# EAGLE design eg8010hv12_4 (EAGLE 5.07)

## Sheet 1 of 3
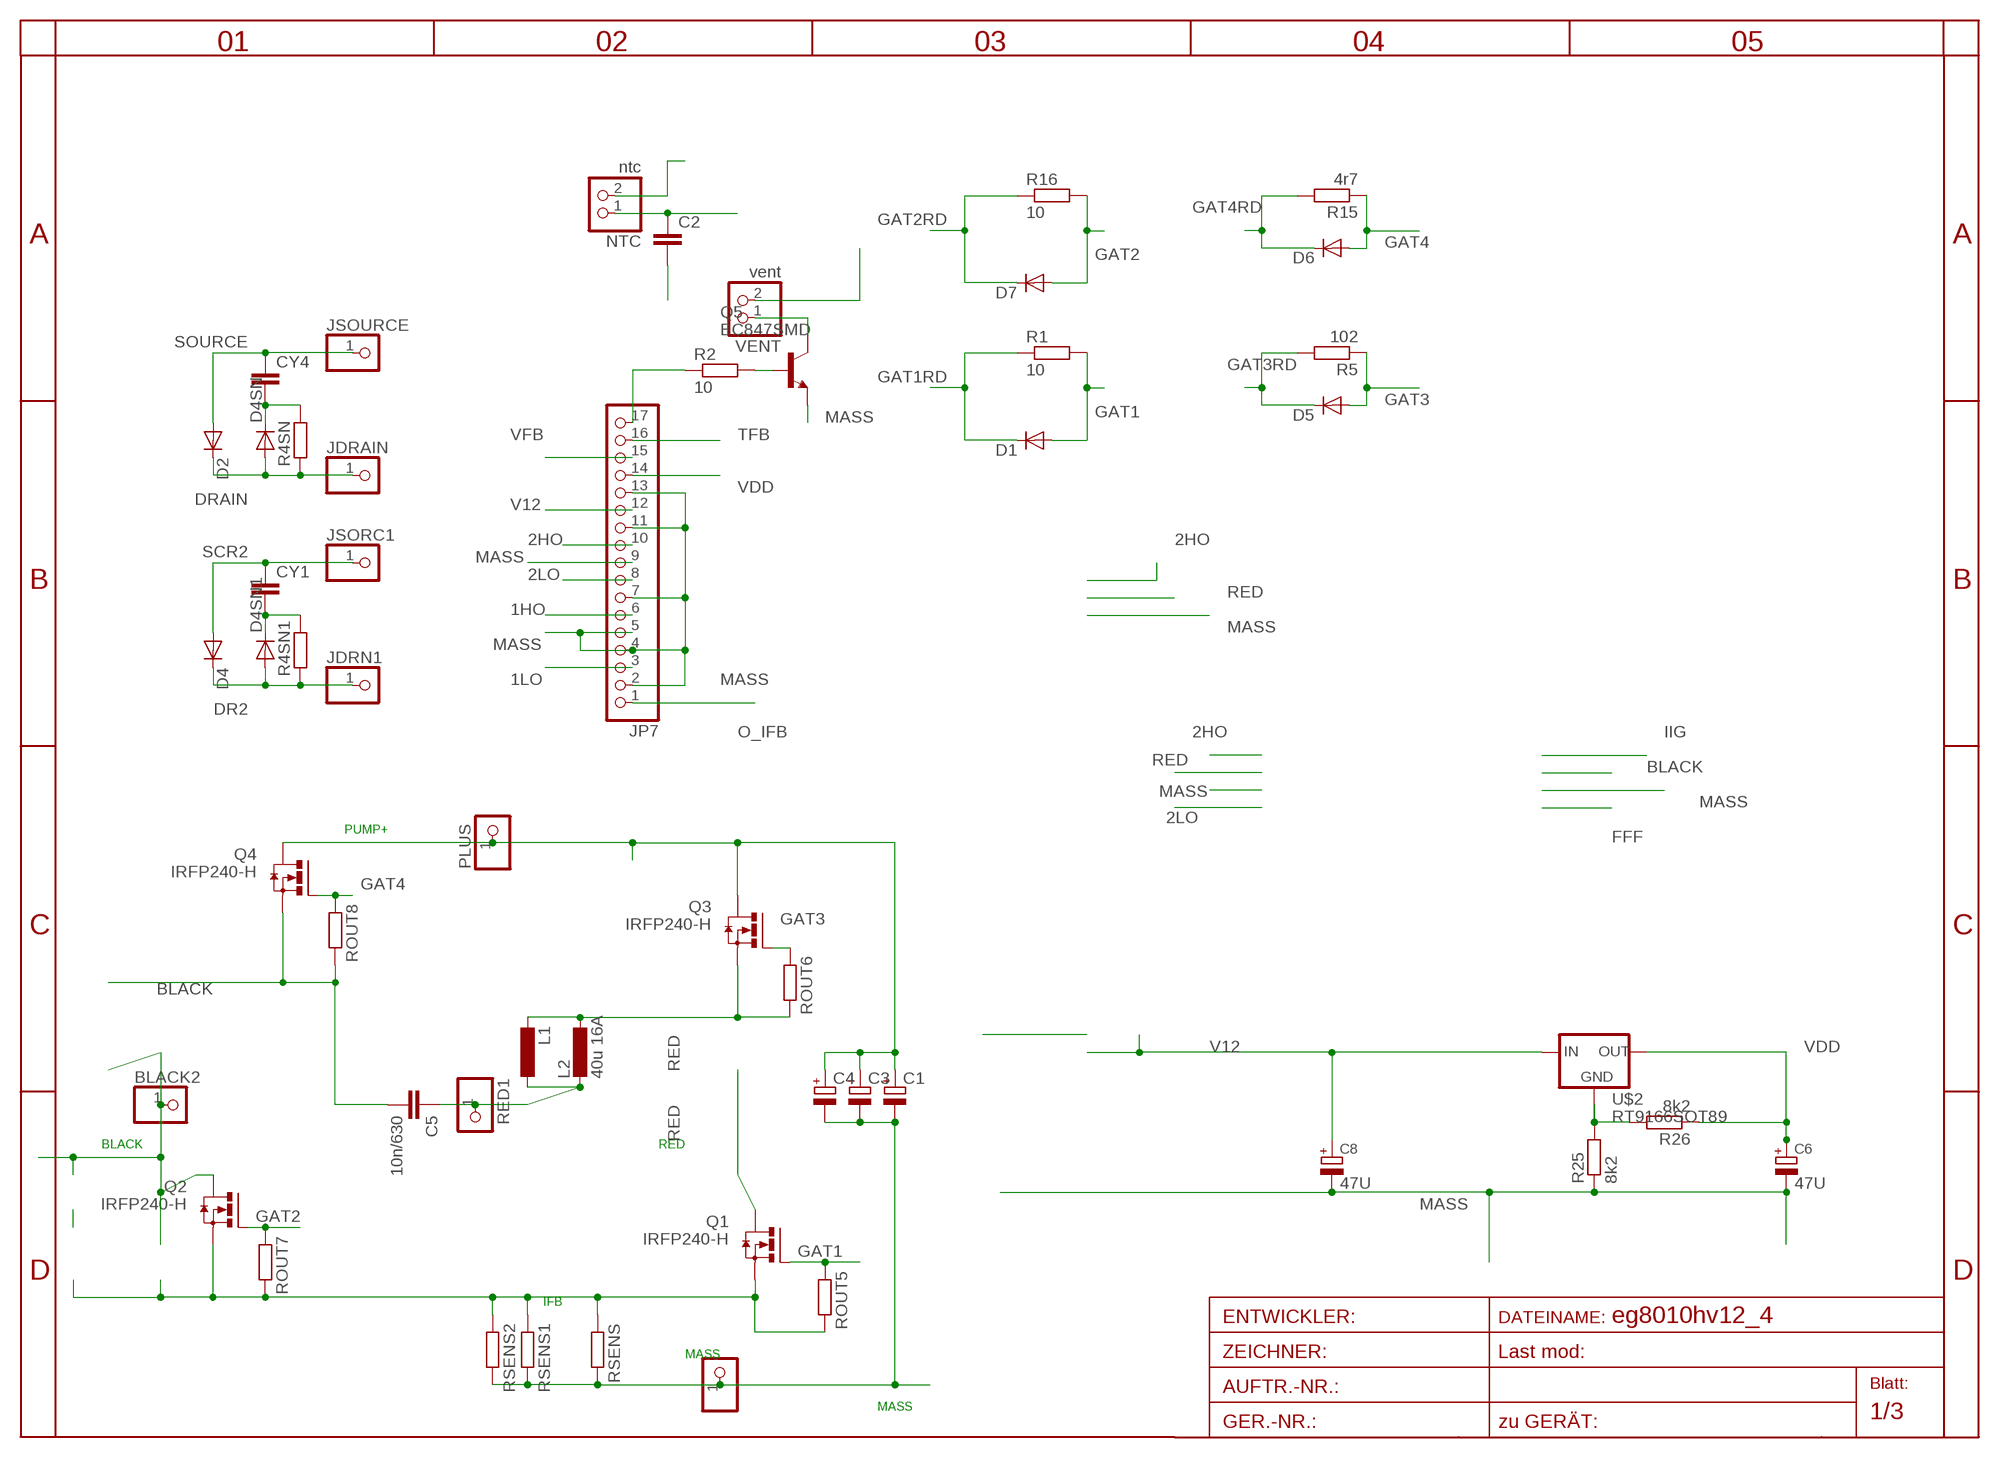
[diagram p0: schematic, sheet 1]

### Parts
BLACK2  PINHD-1X12MM3  [1X2MM3]
C1  CPOL-EUE5-13  [E5-13]
C2  C-EUC1206  [C1206]
C3  CPOL-EUE5-13  [E5-13]
C4  CPOL-EUE5-13  [E5-13]
C5  10n/630  C-EU275-173X316  [C275-173X316]
C6  47U  CPOL-EUSMCA  [SMC_A]
C8  47U  CPOL-EUSMCA  [SMC_A]
CY1  CXXC10B5  [XC10B5]
CY4  CXXC10B5  [XC10B5]
D1  DIODE-SMA-DO214  [SMA-DO214AC]
D2  DIODE-SMC  [SMC]
D4  DIODE-SMC  [SMC]
D4SN  DIODE-P1-10  [P1-10]
D4SN1  DIODE-P1-10  [P1-10]
D5  DIODE-MINIMELF  [MINIMELF]
D6  DIODE-SMA-DO214  [SMA-DO214AC]
D7  DIODE-SMA-DO214  [SMA-DO214AC]
JDRAIN  PINHD-1X11MM0  [1X1MM0]
JDRN1  PINHD-1X11MM0  [1X1MM0]
JP7  PINHD-1X17  [1X17]
JSORC1  PINHD-1X11MM0  [1X1MM0]
JSOURCE  PINHD-1X11MM0  [1X1MM0]
L1  L-EU4.13  [0204/13]
L2  40u 16A  L-EURNG  [RING]
MINUS  PINHD-1X12MM3  [1X2MM3]
NTC  ntc  PINHD-1X2STR  [1X02]
PLUS  PINHD-1X12MM3  [1X2MM3]
Q1  IRFP240-H  [TO247BH]
Q2  IRFP240-H  [TO247BH]
Q3  IRFP240-H  [TO247BH]
Q4  IRFP240-H  [TO247BH]
Q5  BC847SMD  [SOT23]
R1  10  R-EU_R1206  [R1206]
R2  10  R-EU_R0805  [R0805]
R4SN  R-EU_0207/10  [0207/10]
R4SN1  R-EU_0207/10  [0207/10]
R5  102  R-EU_R1206  [R1206]
R15  4r7  R-EU_R1206  [R1206]
R16  10  R-EU_R1206  [R1206]
R25  8k2  R-EU_R0805  [R0805]
R26  8k2  R-EU_R0805  [R0805]
RED1  PINHD-1X12MM3  [1X2MM3]
ROUT5  R-EU_R1206  [R1206]
ROUT6  R-EU_R1206  [R1206]
ROUT7  R-EU_R1206  [R1206]
ROUT8  R-EU_R1206  [R1206]
RSENS  R-EU_0204/7  [0204/7]
RSENS1  R-EU_0204/7  [0204/7]
RSENS2  R-EU_0922V  [0922V]
U$2  RT9166SOT89  [SOT89R]
VENT  vent  PINHD-1X2STR  [1X02]

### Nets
1HO: JP7.6 ; also sheet 3
1LO: JP7.3 ; also sheet 3
2HO: JP7.10 ; also sheet 3
2LO: JP7.8 ; also sheet 3
ACL: C5.1 L1.1 L2.2 RED1.1 ; also sheet 3
BLACK: BLACK2.1 C5.2 Q2.D Q4.S ROUT8.2 ; also sheet 3
DR2: D4.C D4SN1.A JDRN1.1 R4SN1.1
DRAIN: D2.C D4SN.A JDRAIN.1 R4SN.1
FANCTR: JP7.17 R2.1 ; also sheet 3
GAT1: D1.A Q1.G R1.2 ROUT5.1
GAT1RD: D1.K(C) R1.1 ; also sheet 3
GAT2: D7.A Q2.G R16.2 ROUT7.1
GAT2RD: D7.K(C) R16.1 ; also sheet 3
GAT3: D5.A Q3.G R5.1 ROUT6.1
GAT3RD: D5.C R5.2 ; also sheet 3
GAT4: D6.A Q4.G R15.1 ROUT8.1
GAT4RD: D6.K(C) R15.2 ; also sheet 3
IFB: Q1.S Q2.S ROUT5.2 ROUT7.2 RSENS1.1 RSENS2.1 RSENS.1 ; also sheet 2,3
MASS: C1.- C2.2 C3.- C4.- C6.- C8.- JP7.2 JP7.4 JP7.5 JP7.7 JP7.9 JP7.11 JP7.13 MINUS.1 Q5.2(E) R25.1 RSENS1.2 RSENS2.2 RSENS.2 ; also sheet 2,3
N$1: Q5.3(C) VENT.1
N$2: Q5.1(B) R2.2
N$17: R25.2 R26.2 U$2.3(GND) U$2.4(GND1)
O_IFB: JP7.1 ; also sheet 2,3
PUMP+: C1.+ C3.+ C4.+ PLUS.1 Q3.D Q4.D ; also sheet 2
RED: L1.2 L2.1 Q1.D Q3.S ROUT6.2 ; also sheet 3
SCR2: CY1.1 D4.A JSORC1.1
SNUB1: CY1.2 D4SN1.C R4SN1.2
SNUB2: CY4.2 D4SN.C R4SN.2
SOURCE: CY4.1 D2.A JSOURCE.1
TFB: C2.1 JP7.16 NTC.1 ; also sheet 3
V12: C8.+ JP7.12 U$2.1(IN) ; also sheet 2,3
VDD: C6.+ JP7.14 NTC.2 R26.1 U$2.2(OUT) VENT.2 ; also sheet 3
VFB: JP7.15 ; also sheet 3

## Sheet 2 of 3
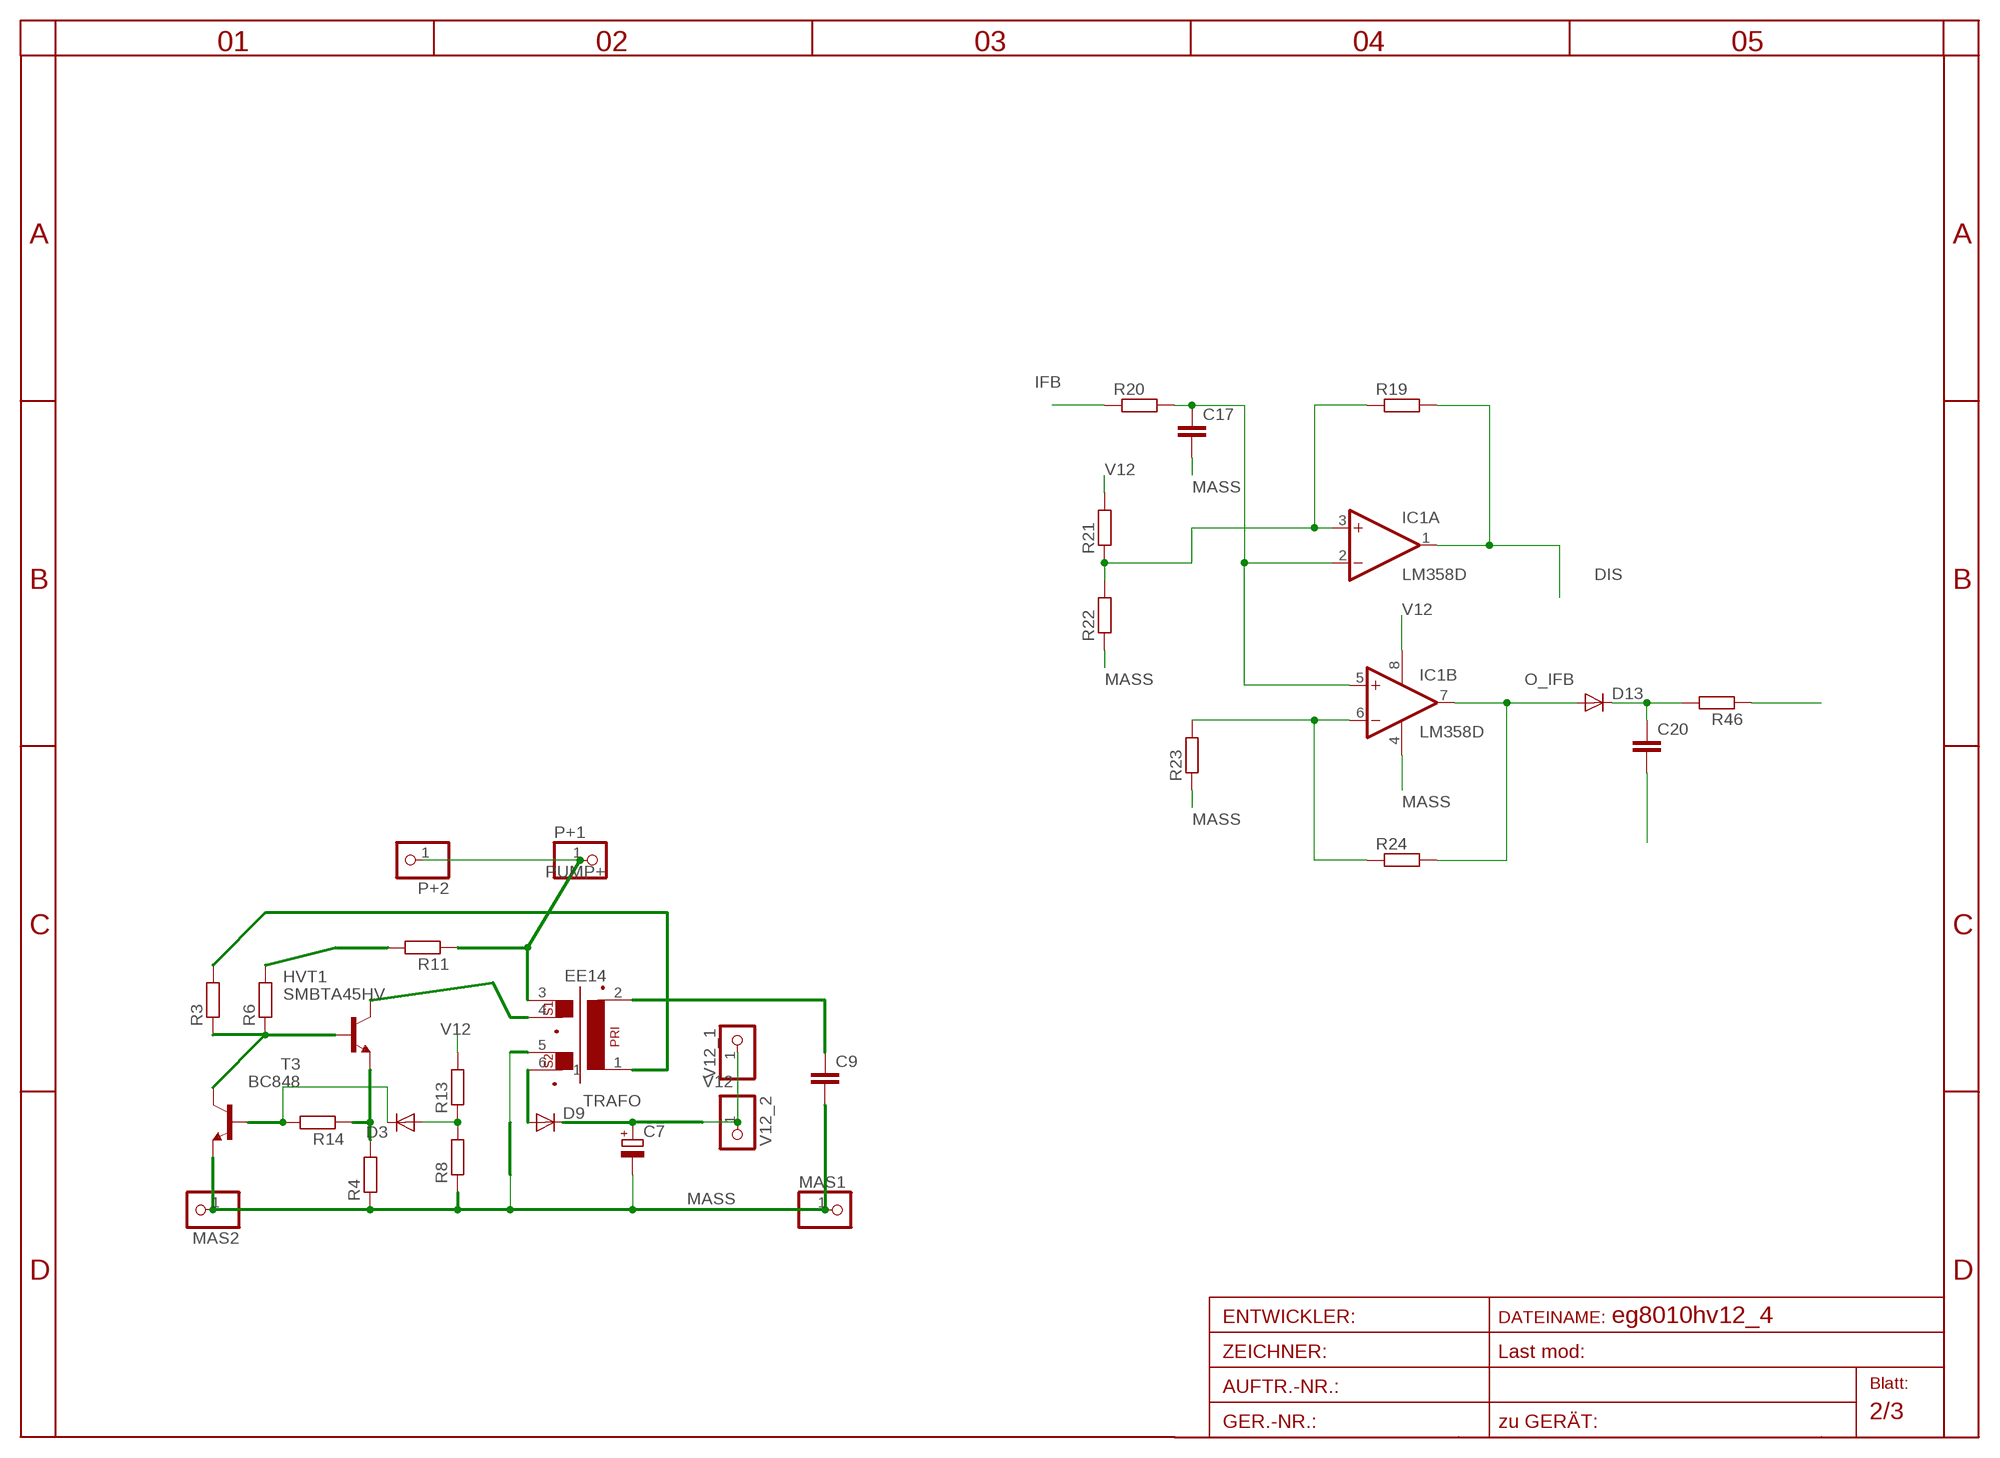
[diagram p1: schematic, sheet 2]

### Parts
C7  CPOL-EUSMCA  [SMC_A]
C9  C-EUC0805  [C0805]
C17  C-EUC1206  [C1206]
C20  C-EUC0805  [C0805]
D3  DIODE-MINIMELF  [MINIMELF]
D9  DIODE-SMA-DO214  [SMA-DO214AC]
D13  DIODE-MINIMELF  [MINIMELF]
HVT1  SMBTA45HV  [SOT23HV]
IC1  LM358D  [SO08]
MAS1  PINHD-1X11X0.4  [1X01]
MAS2  PINHD-1X11X0.4  [1X01]
P+1  PINHD-1X11X0.4  [1X01]
P+2  PINHD-1X11X0.4  [1X01]
R3  R-EU_R0805  [R0805]
R4  R-EU_R0805  [R0805]
R6  R-EU_R1206  [R1206]
R8  R-EU_R0805  [R0805]
R11  R-EU_R1206  [R1206]
R13  R-EU_R0805  [R0805]
R14  R-EU_R0805  [R0805]
R19  R-EU_R1206  [R1206]
R20  R-EU_R0805  [R0805]
R21  R-EU_R0805  [R0805]
R22  R-EU_R0805  [R0805]
R23  R-EU_R0805  [R0805]
R24  R-EU_R0805  [R0805]
R46  R-EU_R0805  [R0805]
T3  BC848  [SOT23]
TRAFO  EE14  [EE14]
V12_1  PINHD-1X11X0.4  [1X01]
V12_2  PINHD-1X11X0.4  [1X01]

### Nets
A: D9.A TRAFO.6
B1C2: HVT1.1(B) R3.1 R6.1 T3.C
BT1: D3.C R14.2 T3.B
C1: HVT1.3(C) TRAFO.4
DIS: IC1.1(A:OUT) R19.2 ; also sheet 3
EB: HVT1.2(E) R4.2 R14.1
IFB: R20.1 ; also sheet 1,3
IFB8010: R46.1 ; also sheet 3
MASS: C7.- C9.2 C17.2 C20.2 IC1.4(P:V-) MAS1.1 MAS2.1 R4.1 R8.1 R22.1 R23.1 T3.E TRAFO.5 ; also sheet 1,3
N$6: R3.2 TRAFO.1
N$7: C9.1 TRAFO.2
N$8: R6.2 R11.2
N$9: IC1.3(A:+IN) R19.1 R21.1 R22.2
N$10: D3.A R8.2 R13.1
N$15: C17.1 IC1.2(A:-IN) IC1.5(B:+IN) R20.2
N$18: IC1.6(B:-IN) R23.2 R24.1
N$40: C20.1 D13.C R46.2
O_IFB: D13.A IC1.7(B:OUT) R24.2 ; also sheet 1,3
PUMP+: P+1.1 P+2.1 R11.1 TRAFO.3 ; also sheet 1
V12: C7.+ D9.K(C) IC1.8(P:V+) R13.2 R21.2 V12_1.1 V12_2.1 ; also sheet 1,3

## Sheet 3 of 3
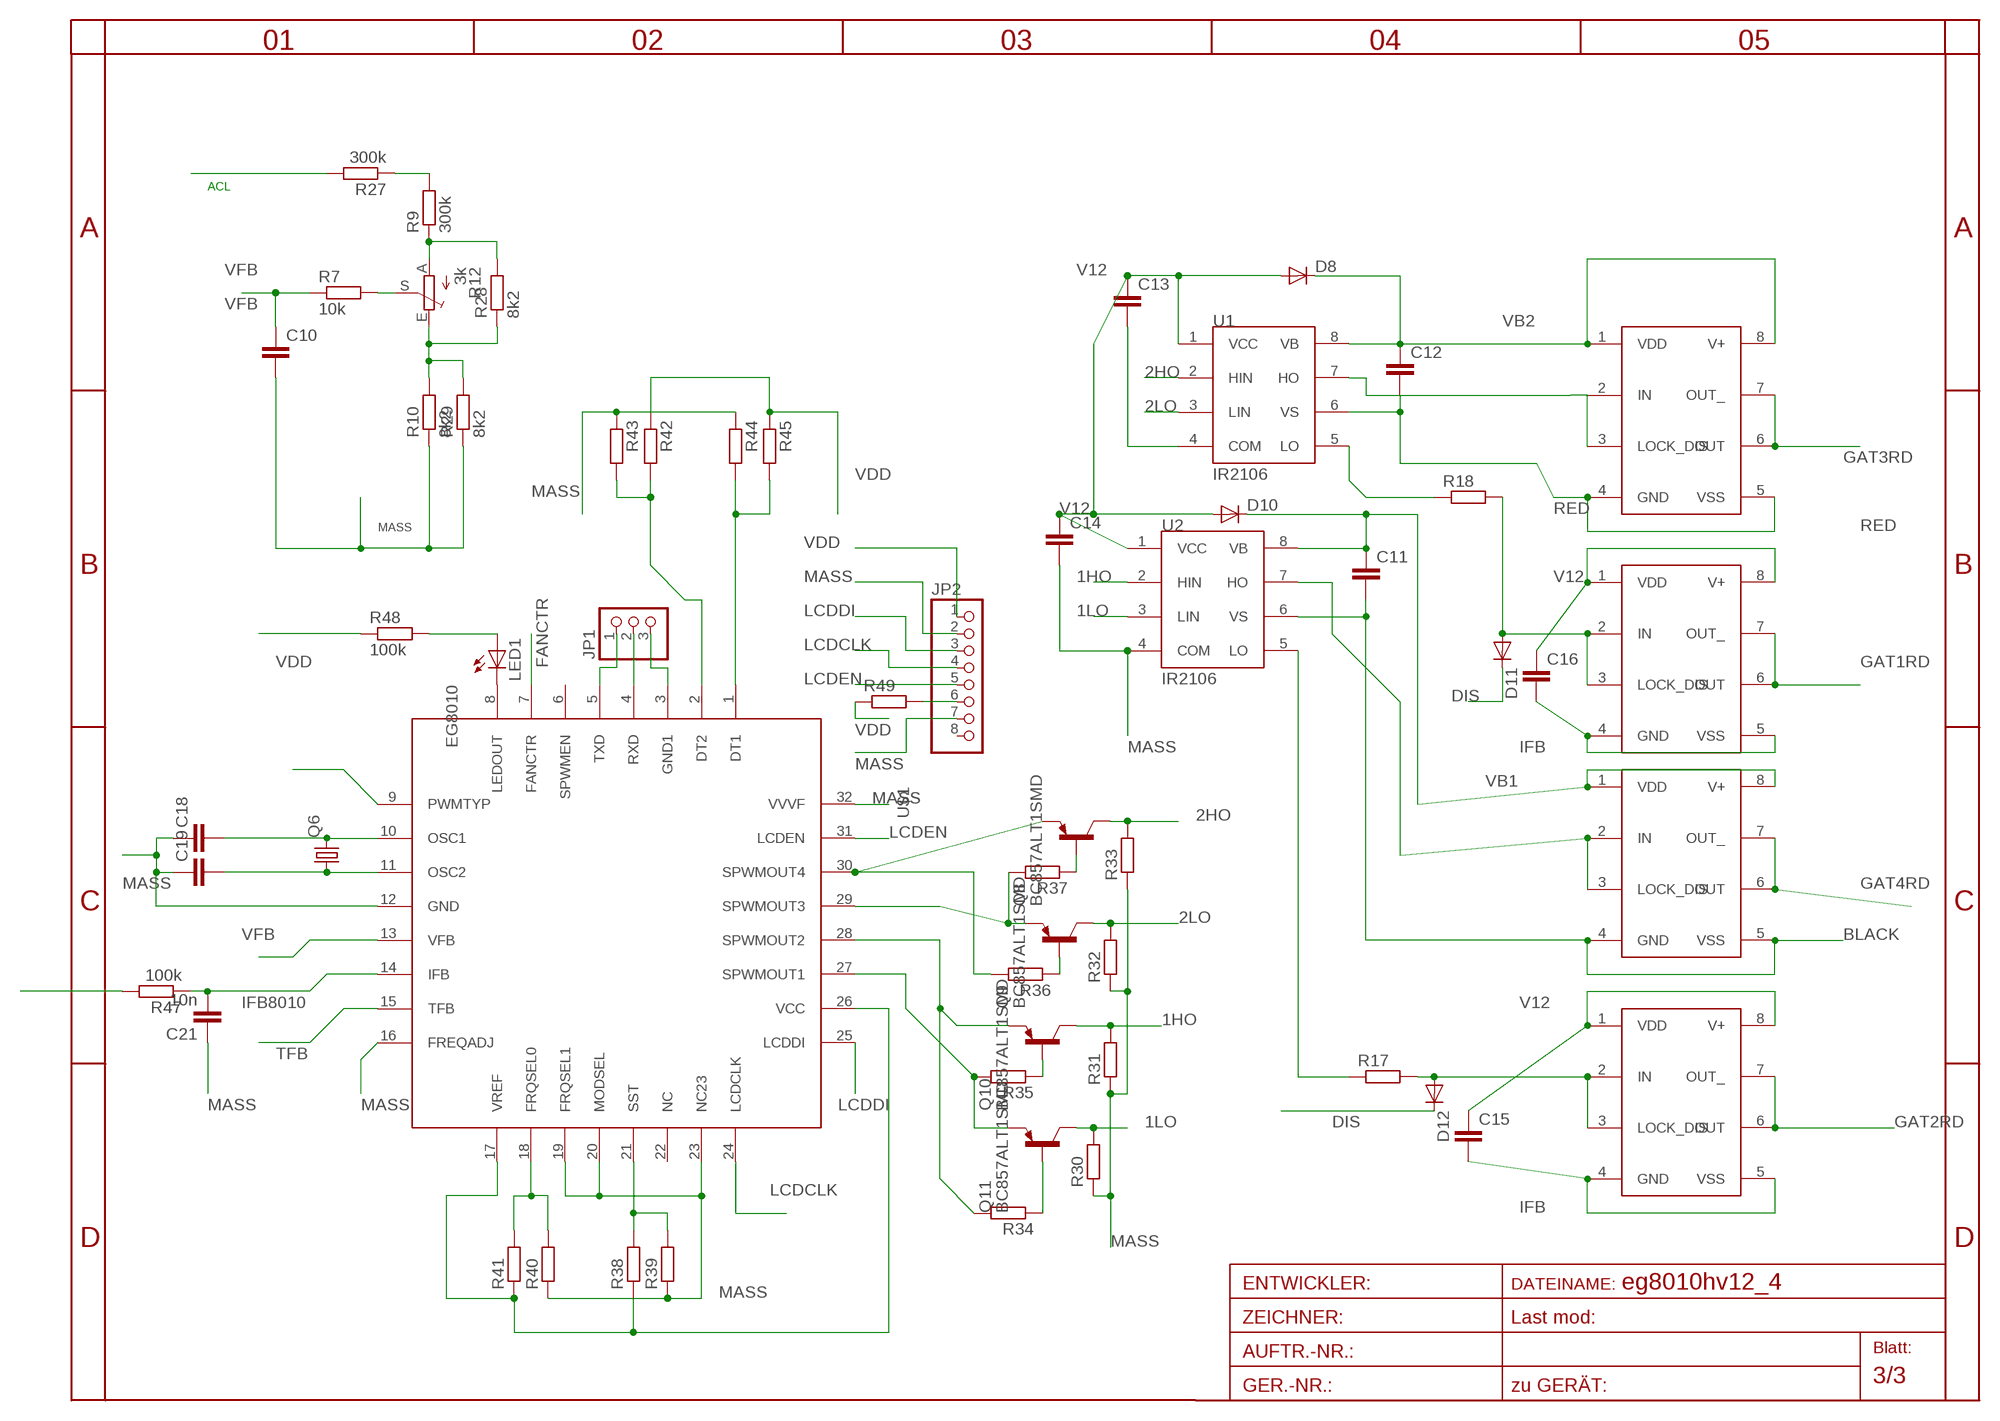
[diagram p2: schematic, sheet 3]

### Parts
1HDRV  TC4432X  [SO-08]
1LODRV  TC4432X  [SO-08]
2HDRV  TC4432X  [SO-08]
2LODRV  TC4432X  [SO-08]
C10  C-EUC0805  [C0805]
C11  C-EUC1206  [C1206]
C12  C-EUC1206  [C1206]
C13  C-EUC1206  [C1206]
C14  C-EUC1206  [C1206]
C15  C-EUC1206  [C1206]
C16  C-EUC1206  [C1206]
C18  C-EUC1206  [C1206]
C19  C-EUC1206  [C1206]
C21  10n  C-EUC1206  [C1206]
D8  DIODE-SMA-DO214  [SMA-DO214AC]
D10  DIODE-SMA-DO214  [SMA-DO214AC]
D11  DIODE-MINIMELF  [MINIMELF]
D12  DIODE-MINIMELF  [MINIMELF]
JP1  PINHD-1X3  [1X03]
JP2  PINHD-1X8  [1X08]
LED1  LEDCHIPLED_1206  [CHIPLED_1206]
Q6  CRYSTALHC49S  [HC49/S]
Q8  BC857ALT1SMD  [SOT23-BEC]
Q9  BC857ALT1SMD  [SOT23-BEC]
Q10  BC857ALT1SMD  [SOT23-BEC]
Q11  BC857ALT1SMD  [SOT23-BEC]
R7  10k  R-EU_R0805  [R0805]
R9  300k  R-EU_R1206  [R1206]
R10  8k2  R-EU_R0805  [R0805]
R12  3k  TRIM_EU-B64Y  [B64Y]
R17  R-EU_0617/17  [0617/17]
R18  R-EU_0204/5  [0204/5]
R27  300k  R-EU_R1206  [R1206]
R28  8k2  R-EU_R1206  [R1206]
R29  8k2  R-EU_R0805  [R0805]
R30  R-EU_R0805  [R0805]
R31  R-EU_R0805  [R0805]
R32  R-EU_R0805  [R0805]
R33  R-EU_R0805  [R0805]
R34  R-EU_R0805  [R0805]
R35  R-EU_R0805  [R0805]
R36  R-EU_R0805  [R0805]
R37  R-EU_R0805  [R0805]
R38  R-EU_R0402  [R0402]
R39  R-EU_R0402  [R0402]
R40  R-EU_R0402  [R0402]
R41  R-EU_R0402  [R0402]
R42  R-EU_R0402  [R0402]
R43  R-EU_R0402  [R0402]
R44  R-EU_R0402  [R0402]
R45  R-EU_R0402  [R0402]
R47  100k  R-EU_R0805  [R0805]
R48  100k  R-EU_R0805  [R0805]
R49  R-EU_R0402  [R0402]
U1  IR2106  [SO8-2]
U2  IR2106  [SO8-2]
U$1  EG8010  [EG8010-32]

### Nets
1HO: Q10.C R31.2 U2.2(HIN) ; also sheet 1
1LO: Q11.C R30.2 U2.3(LIN) ; also sheet 1
2HO: Q8.C R33.2 U1.2(HIN) ; also sheet 1
2LO: Q9.C R32.2 U1.3(LIN) ; also sheet 1
ACL: R27.2 ; also sheet 1
BLACK: 1HDRV.4(GND) 1HDRV.5(VSS) C11.2 U2.6(VS) ; also sheet 1
DIS: D11.C D12.C ; also sheet 2
FANCTR: U$1.7(FANCTR) ; also sheet 1
GAT1RD: 2LODRV.6(OUT) 2LODRV.7(OUT_) ; also sheet 1
GAT2RD: 1LODRV.6(OUT) 1LODRV.7(OUT_) ; also sheet 1
GAT3RD: 2HDRV.6(OUT) 2HDRV.7(OUT_) ; also sheet 1
GAT4RD: 1HDRV.6(OUT) 1HDRV.7(OUT_) ; also sheet 1
IFB: 1LODRV.4(GND) 1LODRV.5(VSS) 2LODRV.4(GND) 2LODRV.5(VSS) C15.2 C16.2 ; also sheet 1,2
IFB8010: C21.2 R47.1 U$1.14(IFB) ; also sheet 2
LCDCLK: JP2.4 U$1.24(LCDCLK)
LCDDI: JP2.3 U$1.25(LCDDI)
LCDEN: JP2.5 U$1.31(LCDEN)
MASS: C10.2 C13.2 C14.2 C18.1 C19.1 C21.1 JP1.3 JP2.2 JP2.7 R10.1 R29.1 R30.1 R31.1 R32.1 R33.1 R39.1 R40.1 R43.1 R44.1 U1.4(COM) U2.4(COM) U$1.3(GND1) U$1.9(PWMTYP) U$1.12(GND) U$1.16(FREQADJ) U$1.19(FRQSEL1) U$1.20(MODSEL) U$1.23(NC23) U$1.32(VVVF) ; also sheet 1,2
N$3: JP1.1 U$1.5(TXD)
N$4: R18.1 U1.5(LO)
N$5: 1LODRV.2(IN) 1LODRV.3(LOCK_DIS) D12.A R17.2
N$11: R17.1 U2.5(LO)
N$12: 2HDRV.2(IN) 2HDRV.3(LOCK_DIS) U1.7(HO)
N$13: 1HDRV.2(IN) 1HDRV.3(LOCK_DIS) U2.7(HO)
N$16: 2LODRV.2(IN) 2LODRV.3(LOCK_DIS) D11.A R18.2
N$19: C19.2 Q6.1 U$1.11(OSC2)
N$20: C18.2 Q6.2 U$1.10(OSC1)
N$21: Q8.E R36.2 U$1.30(SPWMOUT4)
N$22: Q9.E R37.2 U$1.29(SPWMOUT3)
N$23: R9.2 R27.1
N$24: LED1.C U$1.8(LEDOUT)
N$25: Q8.B R37.1
N$26: Q9.B R36.1
N$27: R40.2 R41.2 U$1.18(FRQSEL0)
N$28: LED1.A R48.2
N$29: R10.2 R12.E R28.1 R29.2
N$30: R9.1 R12.A R28.2
N$31: R7.2 R12.S
N$32: R38.2 R39.2 U$1.21(SST)
N$33: Q10.E R34.2 U$1.28(SPWMOUT2)
N$34: Q10.B R35.1
N$35: Q11.E R35.2 U$1.27(SPWMOUT1)
N$36: Q11.B R34.1
N$37: JP1.2 U$1.4(RXD)
N$38: R44.2 R45.2 U$1.1(DT1)
N$39: R42.2 R43.2 U$1.2(DT2)
N$42: JP2.6 R49.2
O_IFB: R47.2 ; also sheet 1,2
RED: 2HDRV.4(GND) 2HDRV.5(VSS) C12.2 U1.6(VS) ; also sheet 1
TFB: U$1.15(TFB) ; also sheet 1
V12: 1LODRV.1(VDD) 1LODRV.8(V+) 2LODRV.1(VDD) 2LODRV.8(V+) C13.1 C14.1 C15.1 C16.1 D8.A D10.A U1.1(VCC) U2.1(VCC) ; also sheet 1,2
VB1: 1HDRV.1(VDD) 1HDRV.8(V+) C11.1 D10.K(C) U2.8(VB)
VB2: 2HDRV.1(VDD) 2HDRV.8(V+) C12.1 D8.K(C) U1.8(VB)
VDD: JP2.1 R38.1 R41.1 R42.1 R45.1 R48.1 R49.1 U$1.17(VREF) U$1.26(VCC) ; also sheet 1
VFB: C10.1 R7.1 U$1.13(VFB) ; also sheet 1
Unconnected: JP2.8 U$1.6(SPWMEN) U$1.22(NC)

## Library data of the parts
1HDRV 1LODRV 2HDRV 2LODRV = microchip:TC4432
BLACK2 JDRAIN JDRN1 JSORC1 JSOURCE MAS1 MAS2 MINUS P+1 P+2 PLUS RED1 V12_1 V12_2 = pinhead:PINHD-1X1: PIN HEADER
C1 C3 C4 C6-C8 = rcl:CPOL-EU: POLARIZED CAPACITOR, European symbol
C2 C5 C9-C21 = rcl:C-EU: CAPACITOR, European symbol
CY1 CY4 = rcl:CX: X CAPACITOR
D1-D4 D4SN D4SN1 D5-D13 = diode:DIODE-: DIODE
HVT1 = transistor-npn:SMBTA45
IC1 = linear:LM358: OP AMP also LM158; LM258; LM2904 Source: http://cache.national.com/ds/LM/LM158.pdf
JP1 = pinhead:PINHD-1X3: PIN HEADER
JP2 = pinhead:PINHD-1X8: PIN HEADER
JP7 = pinhead:PINHD-1X17: PIN HEADER
L1 L2 = rcl:L-EU: INDUCTOR, European symbol
LED1 = led:LED: LED
NTC VENT = pinhead:PINHD-1X2: PIN HEADER
Q1-Q4 = transistor-power:IRFP240: HEXFET Power MosFet Source: http://www.irf.com/
Q5 = transistor-npn:BC847*: NPN Transistor
Q6 = crystal:CRYSTAL: CRYSTAL
Q8-Q11 = transistor-pnp:BC857*: PNP Transistror
R1-R4 R4SN R4SN1 R5 R6 R8 R11 R13-R16 R18-R24 R30-R49 ROUT5-ROUT8 RSENS RSENS1 RSENS2 = rcl:R-EU_: RESISTOR, European symbol
R7 R9 R10 R17 R25-R29 = rcl-2:R-EU_: RESISTOR, European symbol
R12 = pot:TRIM_EU-: POTENTIOMETER
T3 = transistor:BC848: NPN TRANSISTOR
TRAFO = trafo:EE14
U1 U2 = irf-2:IR2106
U$1 = texas:EG8010
U$2 = v-reg:RT9166

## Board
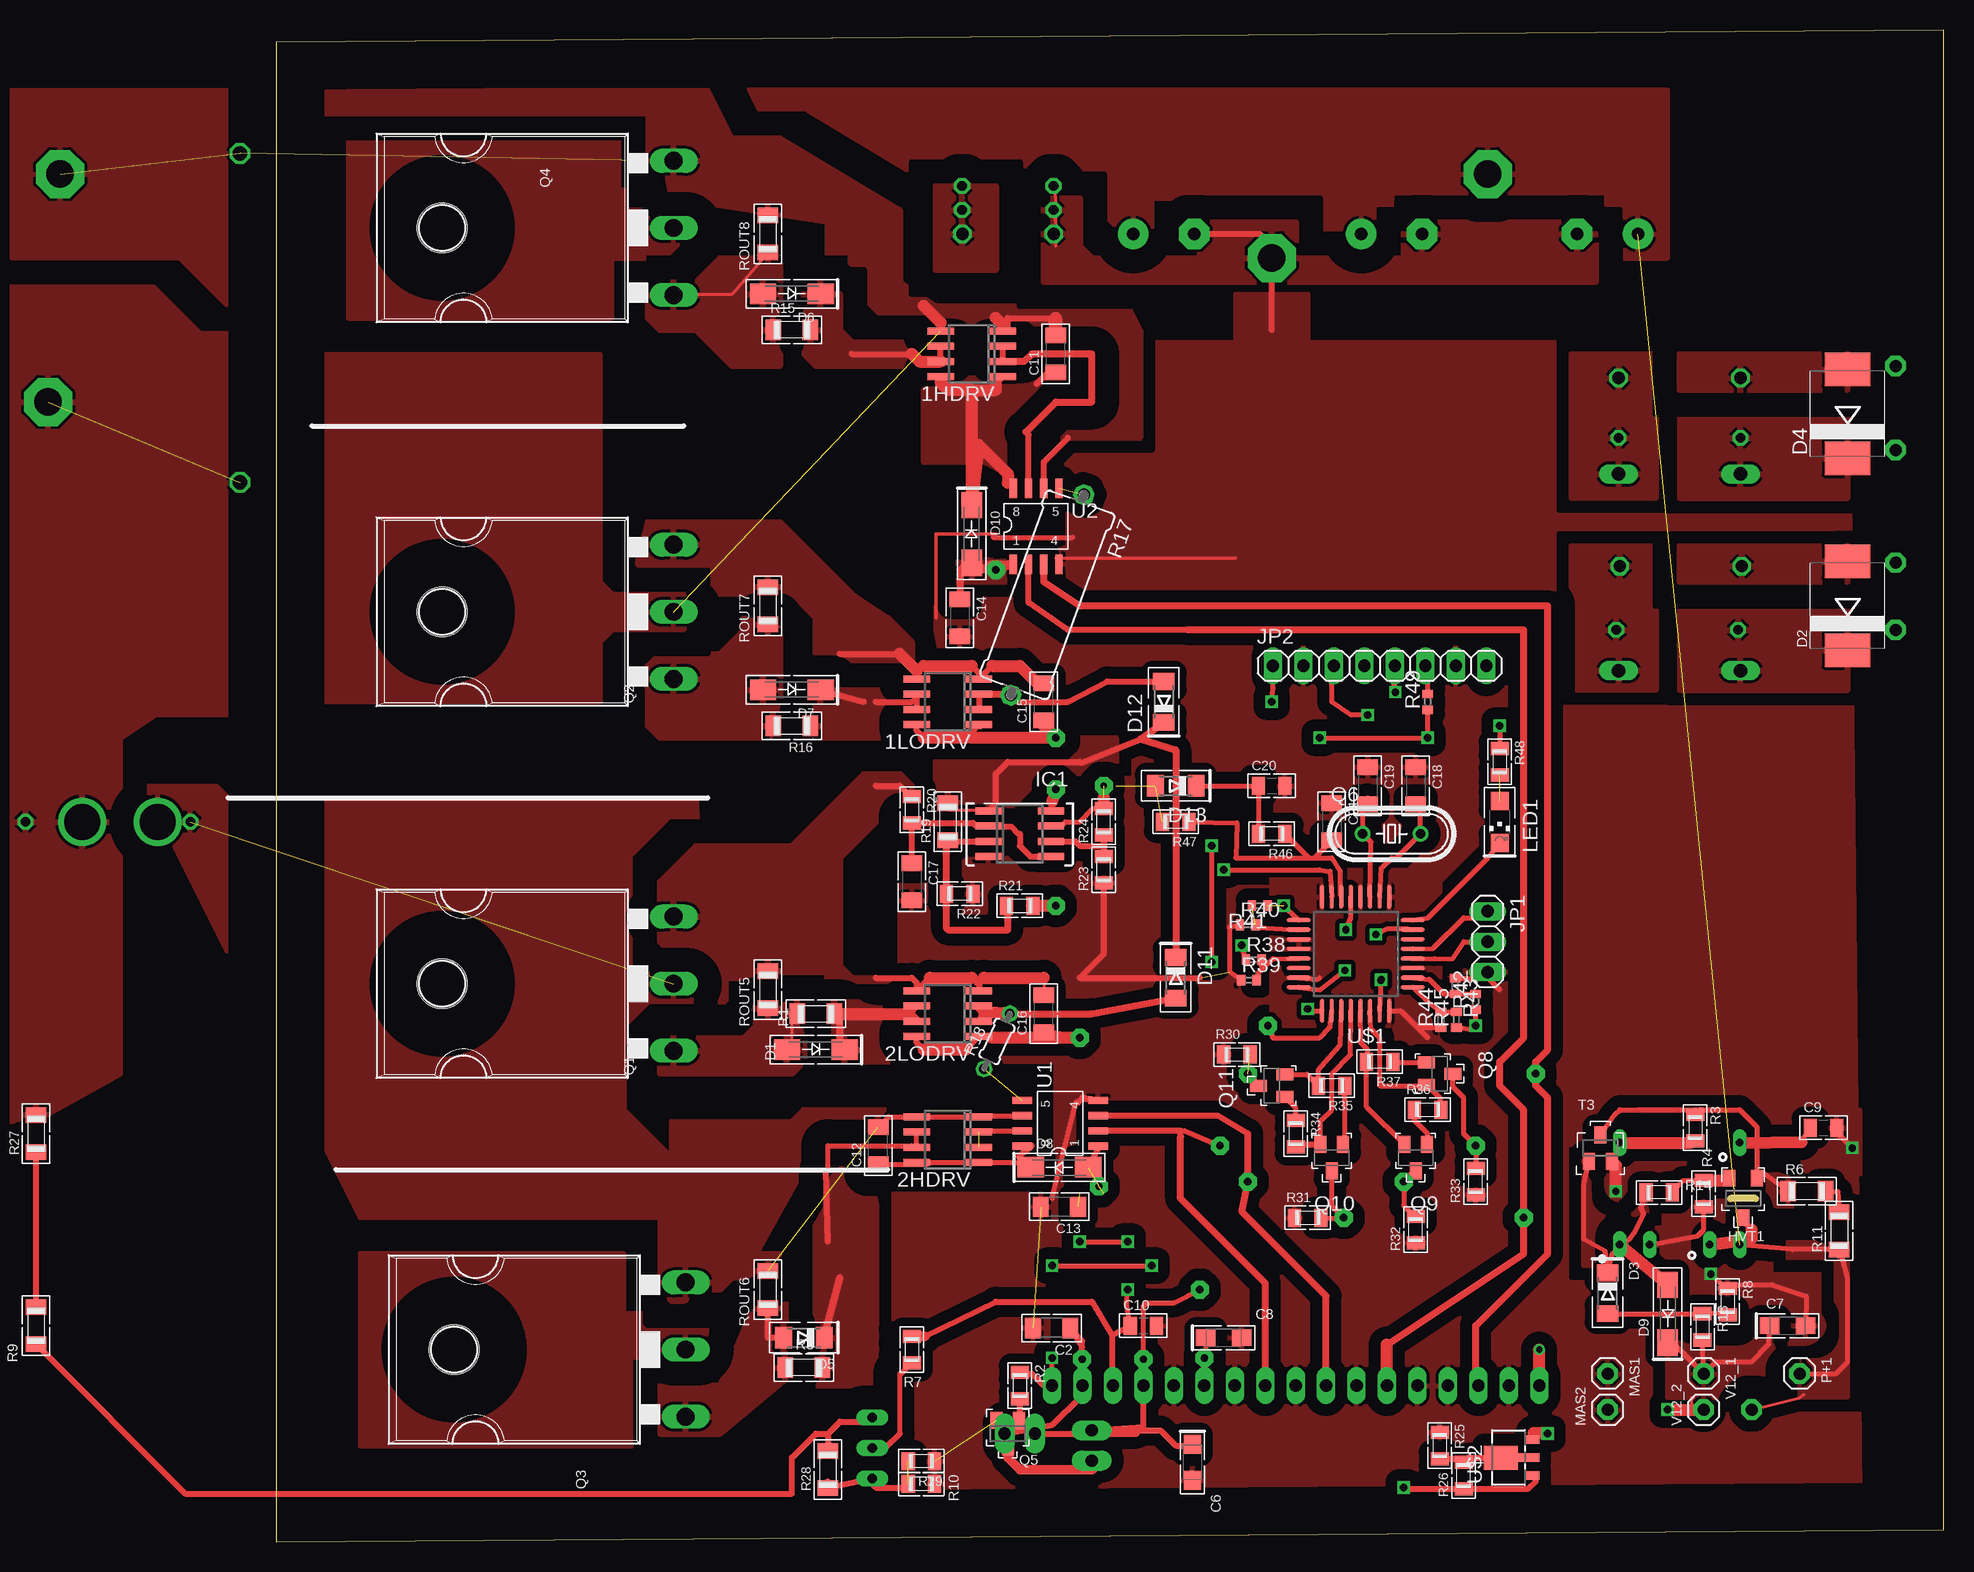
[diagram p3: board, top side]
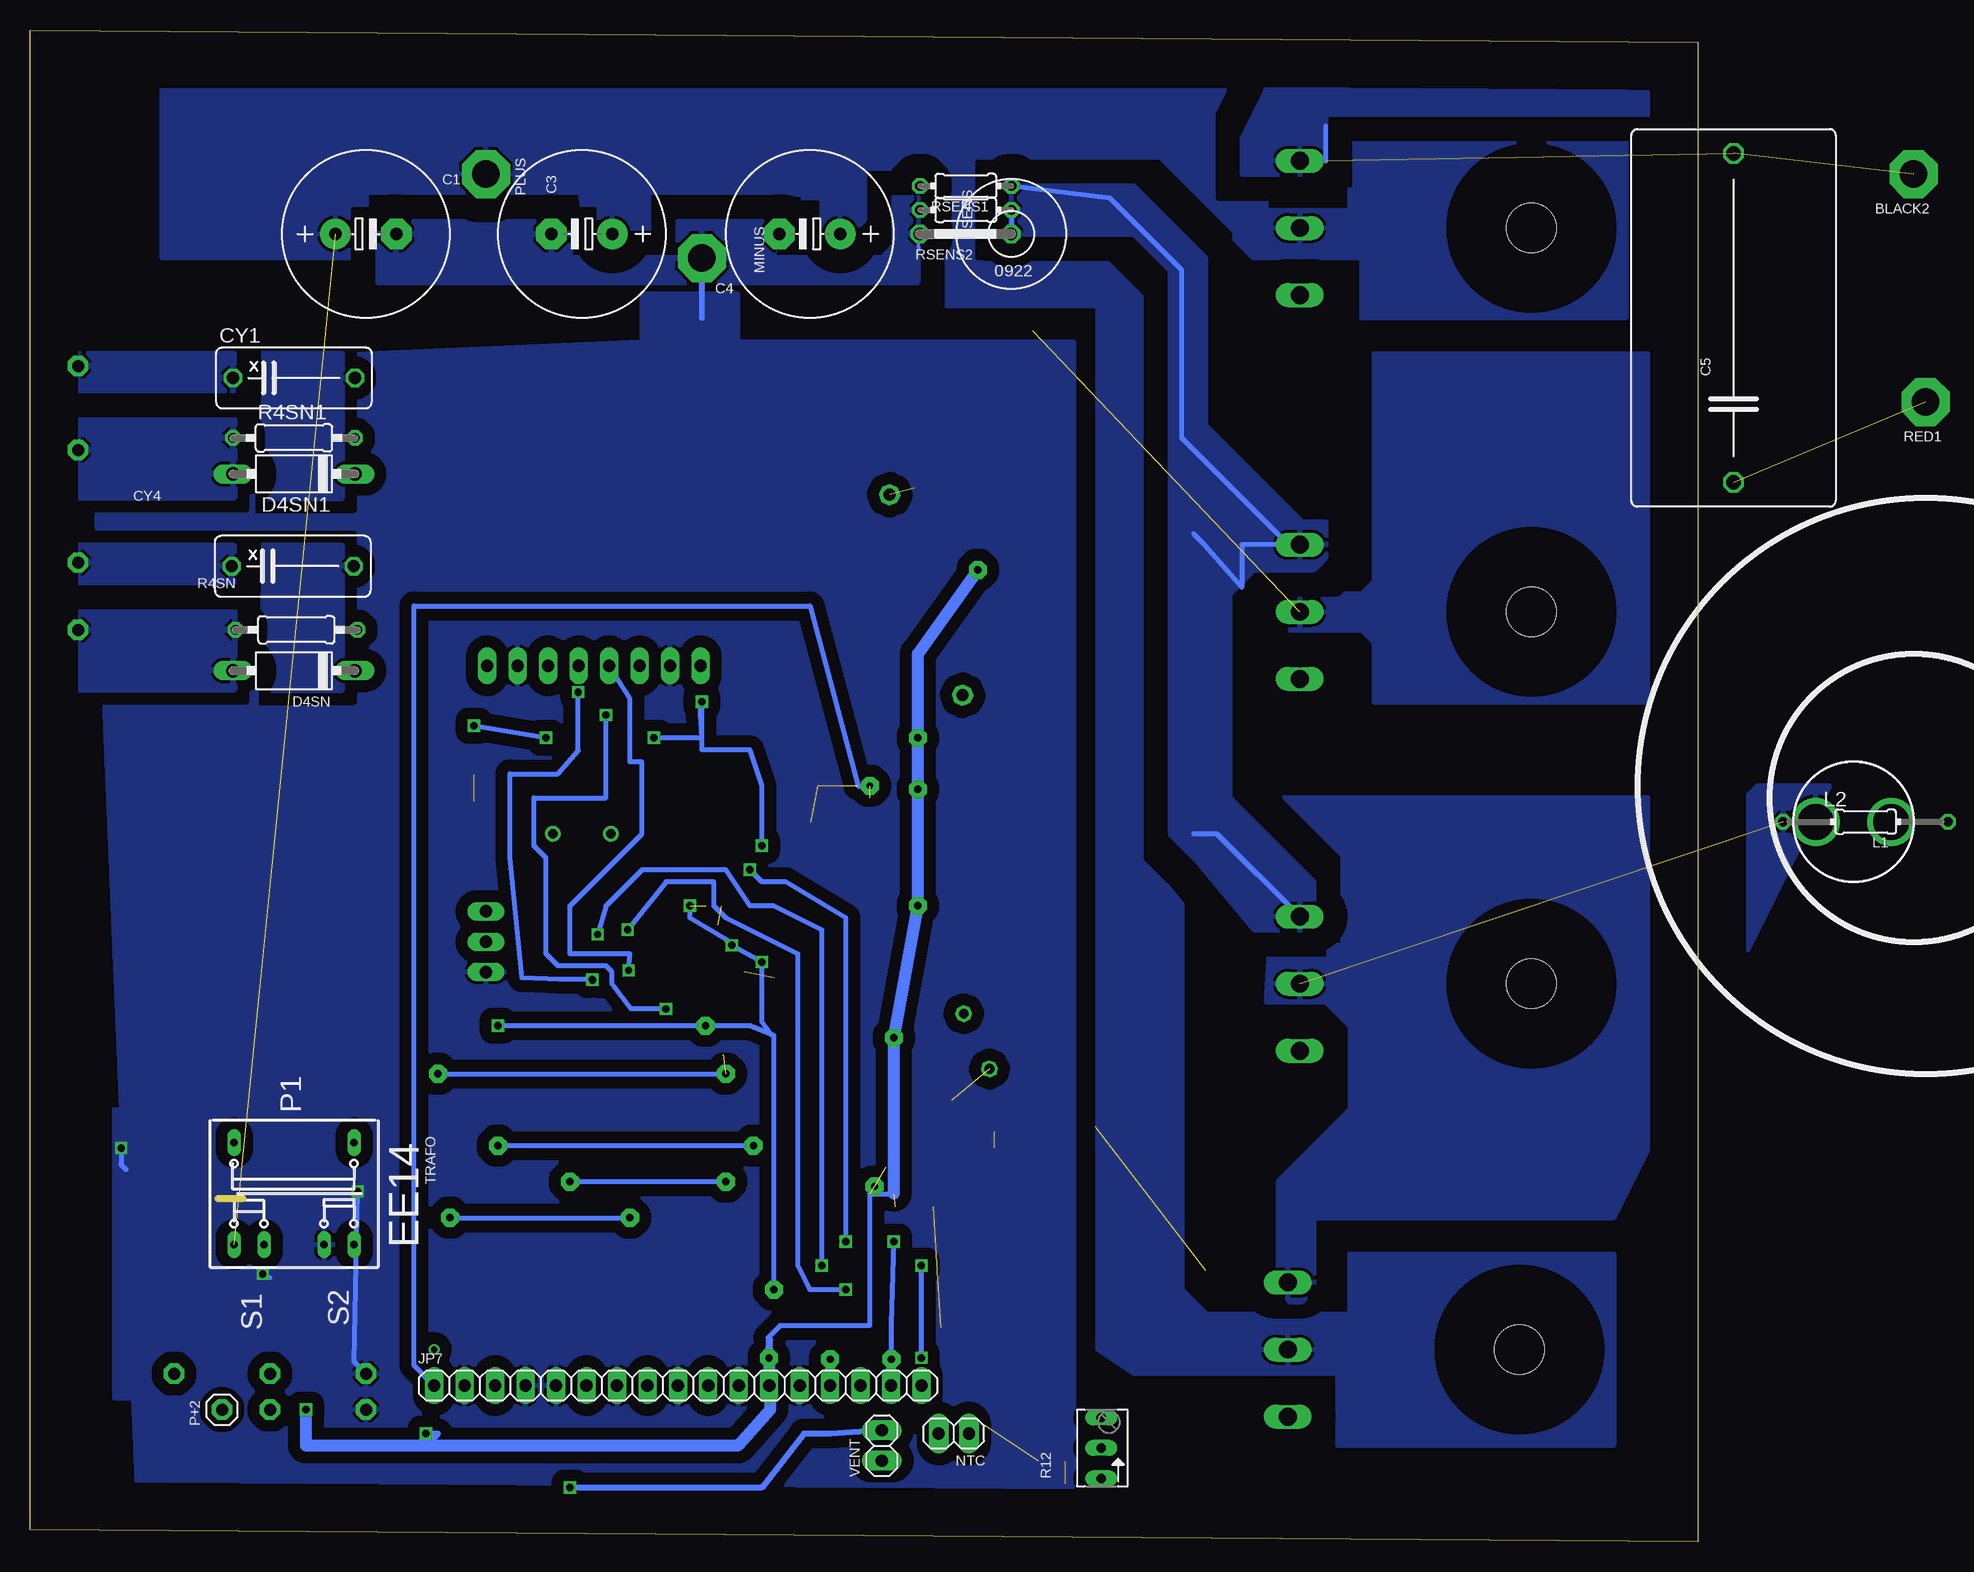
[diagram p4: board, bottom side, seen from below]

Size 139 x 126 mm. Coordinates in mm from the lower left corner, seen from the top.
Outline: 0,0 139,1 139,126 0,125 0,0
Copper layers (1*16): Top 0.035mm / dielectric 1.5mm / Bottom 0.035mm
Design rules "default *": minimum track width 10mil, minimum drill 20mil, track to track 8mil, track to pad 8mil, pad to pad 8mil, via to via 8mil, smd to smd 8mil, copper to edge 4mm, drill to drill 8mil, minimum pad ring 10mil, minimum via ring 8mil, stop-mask expansion 4mil, vias tented up to drill 0mil, thermal gap 10mil

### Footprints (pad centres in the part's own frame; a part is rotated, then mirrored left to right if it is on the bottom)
SO-08 = smd 0.6 x 2.2: 1 -1.905,-2.6; 2 -0.635,-2.6; 3 0.635,-2.6; 4 1.905,-2.6; 5 1.905,2.6; 6 0.635,2.6; 7 -0.635,2.6; 8 -1.905,2.6
1X2MM3 = drill 2.3 pad 4 octagon: 1 0,0
E5-13 = drill 1.016 pad 2.54 round: + -2.54,0 | drill 1.016 pad 2.54 octagon: - 2.54,0
C1206 = smd 1.3 x 1.7: 1 -1.55,0; 2 1.55,0
C275-173X316 = drill 1.194 octagon: 1 -13.716,0; 2 13.716,0
SMC_A = smd 1.6 x 1.4: + -1.5,0; - 1.5,0
C0805 = smd 1.1 x 1.5: 1 -1.1,0; 2 1.1,0
XC10B5 = drill 1.016 octagon: 1 -5.08,0; 2 5.08,0
SMA-DO214AC = smd 2.2 x 1.7: A 2.4,0; K -2.4,0
SMC = smd 2.8 x 3.8: A 3.7,0; C -3.7,0
MINIMELF = smd 1.4 x 1.8: A 1.7,0; C -1.7,0
P1-10 = drill 1.118 long: A 5.08,0; C -5.08,0
SOT23HV = smd 1 x 1.4: 1 -1.15,-1.7; 2 1.15,-1.7; 3 0,1.6
SO08 = smd 0.6 x 2.2: 1 -1.905,-2.6; 2 -0.635,-2.6; 3 0.635,-2.6; 4 1.905,-2.6; 5 1.905,2.6; 6 0.635,2.6; 7 -0.635,2.6; 8 -1.905,2.6
1X1MM0 = drill 1 pad 1.676 octagon: 1 0,0
1X03 = drill 1.016 long: 1 -2.54,0; 2 0,0; 3 2.54,0
1X08 = drill 1.016 long: 1 -8.89,0; 2 -6.35,0; 3 -3.81,0; 4 -1.27,0; 5 1.27,0; 6 3.81,0; 7 6.35,0; 8 8.89,0
1X17 = drill 1.016 long: 1 -20.32,0; 2 -17.78,0; 3 -15.24,0; 4 -12.7,0; 5 -10.16,0; 6 -7.62,0; 7 -5.08,0; 8 -2.54,0; 9 0,0; 10 2.54,0; 11 5.08,0; 12 7.62,0; 13 10.16,0; 14 12.7,0; 15 15.24,0; 16 17.78,0; 17 20.32,0
0204/13 = drill 0.813 octagon: 1 -6.872,0; 2 6.872,0
RING = drill 3 pad 4 round: 1 -3.15,0; 2 3.15,0
CHIPLED_1206 = smd 1.5 x 1.5: A 0,-1.75; C 0,1.75
1X01 = drill 1 pad 1.676 octagon: 1 0,0
1X02 = drill 1.016 pad 1.676 long: 1 -1.27,0; 2 1.27,0
TO247BH = drill 1.499 long: D 0,-10.16; G -5.588,-10.16; S 5.588,-10.16 | hole 4.115: 0,9.144
SOT23 = smd 1 x 1.4: 1 -0.95,-1.1; 2 0.95,-1.1; 3 0,1.1
HC49/S = drill 0.813 round: 1 -2.413,0; 2 2.413,0
SOT23-BEC = smd 1 x 1.4: B -0.95,-1.1; C 0,1.1; E 0.95,-1.1
R1206 = smd 1.3 x 1.7: 1 -1.55,0; 2 1.55,0
R0805 = smd 1.1 x 1.5: 1 -1.1,0; 2 1.1,0
0207/10 = drill 0.813 octagon: 1 -5.08,0; 2 5.08,0
B64Y = drill 0.813 long: A 2.54,0; E -2.54,0; S 0,0
0617/17 = drill 1 pad 1.676 octagon: 1 -8.89,0; 2 8.89,0
0204/5 = drill 0.813 octagon: 1 -2.54,0; 2 2.54,0
R0402 = smd 0.7 x 0.9: 1 -0.65,0; 2 0.65,0
0204/7 = drill 0.813 octagon: 1 -3.81,0; 2 3.81,0
0922V = drill 1.016 octagon: 1 -5.08,0; 2 2.54,0
SOT23' = smd 1 x 1.4: B -0.95,-1.1; C 0,1.1; E 0.95,-1.1
EE14 = drill 0.6 pad 1 long: 1 4.25,-5; 2 4.25,5; 3 -4.25,5 | drill 0.6 pad 1.016 long: 4 -4.25,2.5; 5 -4.25,-2.5; 6 -4.25,-5
SO8-2 = smd 0.61 x 1.626: 1 -2.54,-2.54; 2 -1.27,-2.54; 3 0,-2.54; 4 1.27,-2.54; 5 1.27,3.81; 6 0,3.81; 7 -1.27,3.81; 8 -2.54,3.81
EG8010-32 = smd 2 x 0.35: 1 -4.75,2.8; 2 -4.75,2; 3 -4.75,1.2; 4 -4.75,0.4; 5 -4.75,-0.4; 6 -4.75,-1.2; 7 -4.75,-2; 8 -4.75,-2.8; 17 4.75,-2.8; 18 4.75,-2; 19 4.75,-1.2; 20 4.75,-0.4; 21 4.75,0.4; 22 4.75,1.2; 23 4.75,2; 24 4.75,2.8 | smd 0.35 x 2: 9 -2.8,-4.75; 10 -2,-4.75; 11 -1.2,-4.75; 12 -0.4,-4.75; 13 0.4,-4.75; 14 1.2,-4.75; 15 2,-4.75; 16 2.8,-4.75; 25 2.8,4.75; 26 2,4.75; 27 1.2,4.75; 28 0.4,4.75; 29 -0.4,4.75; 30 -1.2,4.75; 31 -2,4.75; 32 -2.8,4.75
SOT89R = smd 0.7 x 1.1: 1 1.5,-1.75; 2 -1.5,-1.75 | smd 0.7 x 1.8: 3 0,-1.4 | smd 2 x 2.8: 4 0,0.9

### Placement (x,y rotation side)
1HDRV  58,99 90 top
1LODRV  56,70 90 top
2HDRV  56,33.5 90 top
2LODRV  56,44 90 top
BLACK2  not placed on the board
C1  111,109 0 bottom
C2  64.65,17.8 180 top
C3  93,109 180 bottom
C4  74,109 180 bottom
C5  -3,102 90 bottom
C6  76.4,6.6 270 top
C7  126,18 0 top
C8  79,17 0 top
C9  129,34.5 0 top
C10  72.3,18 0 top
C11  65,99 90 top
C12  50.2,33 90 top
C13  65.3,27.9 180 top
C14  57,77 270 top
C15  64,70 90 top
C16  64,44 90 top
C17  53,55 270 top
C18  95,63 270 top
C19  91,63 270 top
C20  83,63 0 top
C21  88,60 270 top
CY1  117,97 0 bottom
CY4  117.1,81.3 0 bottom
D1  45,41 180 top
D2  131,78 90 top
D3  111,20.7 270 top
D4  131,94 90 top
D4SN  117,72.6 180 bottom
D4SN1  117,89 180 bottom
D5  44,17 180 top
D6  43,104 180 top
D7  43,71 180 top
D8  65.3,31.2 0 top
D9  116,19 90 top
D10  58,84 270 top
D11  75,47 270 top
D12  74,70 90 top
D13  75,63 180 top
HVT1  122.3,28.6 180 top
IC1  62,59 270 top
JDRAIN  135,76 270 top
JDRN1  135,91 0 top
JP1  101,50 270 top
JP2  92,73 0 top
JP7  85,13 0 bottom
JSORC1  135,98 0 top
JSOURCE  135,81.6 270 top
L1  not placed on the board
L2  not placed on the board
LED1  102,60 180 top
MAS1  111,14 270 top
MAS2  111,11 90 top
MINUS  83,107 270 bottom
NTC  62,9 180 bottom
P+1  127,14 270 top
P+2  123,11 90 bottom
PLUS  101,114 270 bottom
Q1  23,46.5 90 top
Q2  23,77.5 90 top
Q3  24,16 90 top
Q4  23,109.5 90 top
Q5  61,9 180 top
Q6  93,59 0 top
Q8  97,39 270 top
Q9  95,32 180 top
Q10  88,32 180 top
Q11  83,38 90 top
R1  45,44 180 top
R2  62,13 270 top
R3  118.3,34.5 270 top
R4  119,29 90 top
R4SN  116.8,76 0 bottom
R4SN1  117,92 0 bottom
R5  44,14.5 0 top
R6  127.6,29.2 0 top
R7  53,16 270 top
R8  121,20 270 top
R9  -20,18 90 top  (outside the outline)
R10  53.8,4.8 180 top
R11  130.3,25.9 90 top
R12  49.7,7.8 90 bottom
R13  118.9,17.9 270 top
R14  115.3,29.1 180 top
R15  43,101 0 top
R16  43,68 180 top
R17  64.3,78.9 250 top
R18  60.1,41.7 65 top
R19  56,60 90 top
R20  53,61 270 top
R21  62,53 0 top
R22  57,54 180 top
R23  69,56 90 top
R24  69,60 90 top
R25  97,8 270 top
R26  99,5.5 90 top
R27  -20,34 90 top  (outside the outline)
R28  46,6 90 top
R29  53.8,6.7 180 top
R30  80.1,40.6 0 top
R31  86,27 0 top
R32  95,26 90 top
R33  100,30 90 top
R34  85,34 270 top
R35  88,38 180 top
R36  96,36 0 top
R37  92,40 180 top
R38  81.5,48.5 0 top
R39  81.1,46.8 0 top
R40  81,51.4 0 top
R41  82,53 180 top
R42  100,45 90 top
R43  98.3,46.3 270 top
R44  97.1,43.5 90 top
R45  98.4,43.5 90 top
R46  83,59 180 top
R47  75,60 180 top
R48  102,65 270 top
R49  96,70 90 top
RED1  not placed on the board
ROUT5  41,46 90 top
ROUT6  41,21 90 top
ROUT7  41,78 90 top
ROUT8  41,109 90 top
RSENS  61,111 180 bottom
RSENS1  61,113 180 bottom
RSENS2  62.3,109 180 bottom
T3  BC848  [SOT23']  110.4,32.8 0 top
TRAFO  117,29 90 bottom
U1  66,35.5 90 top
U2  64,84 0 top
U$1  90,49 180 top
U$2  103,7 90 top
V12_1  119,14 270 top
V12_2  119,11 90 top
VENT  68,8 90 bottom

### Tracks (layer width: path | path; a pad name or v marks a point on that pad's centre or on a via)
1HO  (via drill 0.6 pad 1.5)
  Top 0.4: R31.2 88.1,26.9 v89,27 88,28 Q10.C
  Top 0.5: U2.2 62.73,78.27 66,76 76,76
  Top 0.6: 92.6,16.4 104,24 v104,27 104,36 102,38 102,40 104,42 104,76 76,76
  Top 1: 92.6,16.4 92.6,14.4 JP7.6
  Bottom 0.4: v104,27 v89,27
1LO  (via drill 0.6 pad 1.5)  (1 unrouted)
  Top 0.4: Q11.C 81.9,38.1 v81,39
  Top 0.6: JP7.3 100,13.76 100,18 106,24 106,37 105,38 v105,39 105,40 106,41 106,78 67,78 64,80 U2.3
  Bottom 0.4: v105,39 v81,39
2HO  (via drill 0.6 pad 1.5)
  Top 0.4: 75.41,34.23 75.77,34.23 v78.7,33 | R33.2 v100,33 99,34 99,37 98.1,37.9 Q8.C
  Top 0.5: U1.2 75.41,34.23 75.41,33.73
  Top 0.6: 75.41,33.73 75.4,28.6 82.46,21.54 JP7.10
  Bottom 0.4: v78.7,33 v100,33
2LO  (via drill 0.6 pad 1.5)
  Top 0.4: Q9.C 94.9,30.9 v94,30 94,28 94.9,27.1 R32.2
  Top 0.5: U1.3 78.5,35.5 81,34
  Top 0.6: 81,34 v81,30 80.54,27.46 87.54,20.46 87.5,19.2 JP7.8
  Bottom 0.4: v81,30 v94,30
A
  Top 1: D9.A TRAFO.6
ACL  (1 unrouted)
  pour Top (isolate 2, rank 2): -21,122 -22,121 -22,34 -13,39 -13,67 -10,69 -3,69 -3,121
B1C2
  Top 0.406: R6.1 124.05,30.7 HVT1.1 123.45,34.55 122,36 118.9,36 | 118.7,36 R3.1 118.9,36 | T3.C 111.6,35.6 112,36 118.7,36 | 118.7,36 118.9,36
  pour Top (isolate 2): 124,31 124,36 109,36 109,33 122,33 122,31 125,28 127,28 127,30
BLACK  (3 unrouted)
  Top 0.5: 1HDRV.5 55.4,101.6 | 60.6,101.4 1HDRV.4 60.91,100.91 61,101 61,102 65,102 64.64,101.64 64.64,100.91 | U2.6 64,90 66,92
  Top 0.6: C11.2 64.64,100.91
  Top 1: 55.4,101.6 54,103 | 60.6,101.4 60,102 | 65,102 C11.2
  Bottom 0.406: Q4.S 31,115.09 31,118
  pour Bottom (isolate 2, rank 2): 38,117 38,114 31,114 31,119 4,119 4,99 27,99 27,80 28,79 34,79 34,76 28,76 27,75 27,70 -1,70 -1,121 36,121
  pour Top (isolate 2, rank 3): 32,117 42,117 52,111 52,105 55,103 71,103 72,101 72,92 65,92 70,99 69,100 52,100 46,106 46,110 33,112
  pour Top (isolate 2): 38,117 38,114 31,114 31,119 4,119 4,99 27,99 27,80 28,79 34,79 34,76 28,76 27,75 27,70 0,70 0,99 -8,107 -22,107 -22,121 36,121
BT1
  Top 0.406: T3.B 109,29.75 109,25.2 110.8,24.2 D3.C 111.4,24 112.9,25.3 113.2,25.7 114,27.3 113.8,27.8 R14.2
  pour Top (isolate 1.5, rank 2): 116,29 116,27 112,23 109,23 109,32 111,32 111,31 113,29
C1
  Top 0.406: HVT1.3 122.3,26.7 123,26
  Top 1: 123,26 123,25.25 TRAFO.4
DIS
  Top 0.254: R19.2 56,61 59,61 IC1.1
  Top 0.5: 75,49 74.9,49 D11.C | 72.1,66.9 67.1,64.9 67,65 61,65 60,64 60,61.51 IC1.1
  Top 0.6: 75,49 75,66 72.1,66.9 D12.C
  pour Top (isolate 1.27, rank 2): 55,67 70,67 70,63 63,63 61,61 55,61 55,66
DR2
  pour Top (isolate 2, rank 2): 131,94 117,94 117,87 131,87
  pour Bottom (isolate 2, rank 2): 136,94 122,94 122,87 136,87
DRAIN
  pour Top (isolate 2, rank 2): 131,78 117,78 117,71 131,71
  pour Bottom (isolate 2, rank 2): 136,78 122,78 122,71 136,71
EB
  Top 0.406: R14.1 117.3,30.1 R4.2 | 120.95,30.1 HVT1.2
  Top 1: R4.2 120.95,30.1
FANCTR  (via drill 0.6)
  Top 0.4: v64.7,23 v73,23 | v91.7,50.6 92.7,51.1 94.31,51.1 U$1.7 | v64.7,15.3 64.7,13.02 JP7.17
  Top 0.5: JP7.17 64,13 63,14 62.1,14 R2.1
  Bottom 0.4: v73,23 73,51 77,53 79,53 81,56 88,56 91,53 v91.7,50.6 | v64.7,15.3 v64.7,23
GAT1
  Top 0.254: R1.2 43,44 43,41 D1.A
  pour Top (isolate 2): 32,42 39,42 40,43 40,45 44,45 44,40 43,39 32,39
GAT1RD
  Top 0.5: 2LODRV.7 53.4,43.6 52.88,44.12
  Top 0.6: 52.77,44 52.88,44.12 2LODRV.6 | R1.1 47,44 47,41.4 D1.K
  Top 1: 47,44 52.77,44
  pour Top (isolate 2, rank 2): 46,45 53,45 52,44 52,40 47,40
GAT2
  pour Top (isolate 2, rank 2): 31,73 32,74 37,74 39,76 39,77 41,77 42,76 42,68 41,67 32,67 31,68 31,70
GAT2RD
  Top 0.5: 1LODRV.7 1LODRV.6 53.4,70.4 53,70 50,70 | D7.K 49,70
  pour Top (isolate 2): 45,71 54,71 54,68 53,67 45,67
GAT3
  Top 0.5: D5.A 41,17 ROUT6.1
  pour Top (isolate 2, rank 3): 32,13 32,9 37,9 43,14 43,20 40,20 37,13
GAT3RD
  Top 0.4: 2HDRV.6 2HDRV.7 53.14,32.87 53,33 46,33 46,31 45.86,30.86
  Top 0.5: 46,25 45.86,30.86
  Top 0.6: D5.C 47,22
  pour Top (isolate 2, rank 2): 45,29 49,33 50,28 50,13 45,13
GAT4
  Top 0.254: Q4.G 34,104 38,104 ROUT8.1
  pour Top (isolate 2, rank 2): 31,105 35,105 37,107 42,107 42,98 38,98 35,101 32,101 31,102
GAT4RD
  Top 0.5: 1HDRV.7 1HDRV.6 | 48,99 53,99
  Top 1: 1HDRV.7 53.64,98.36 53,99
  pour Top (isolate 2, rank 2): 56,98 45,98 44,99 44,104 45,105 46,105 47,104 47,101 48,100 56,100
IFB
  Top 0.254: 64,47 C16.2 | 2LODRV.4 59,47
  Top 0.5: 2LODRV.4 58.6,46.4 58,47 | 54.5,47 2LODRV.5 53.4,46.6 53,47 50,47 | 54,73 53.4,72.4 1LODRV.5 53.4,72.6 | 58,73 59,72 58.69,72 1LODRV.4 59.69,73 | 63.45,71.55 C15.2 | 47,74 52,74 | R20.1 52.9,62.1 52,63 50,63
  Top 1: 59,47 64,47 | 54.5,47 58,47 | 54,73 58,73 | 63.45,71.55 62,73 59.69,73 | 52,74 53.4,72.6
  Bottom 0.406: RSENS.1 57.19,109.59 | Q1.S 40.07,59 42,59 | 42,84 41.08,83.08 38,79.55 37.99,83.09 Q2.S 34.09,83.09 43,92 43,106 49,112 RSENS1.1
  pour Bottom (isolate 2): 58,113 58,109 47,109 44,106 44,59 42,57 37,51 33,51 32,52 32,55 39,62 39,79 37,81 32,81 31,82 31,85 33,85 41,93 41,107 47,113
  pour Top (isolate 2, rank 2): 55,113 60,113 60,106 55,106
  pour Top (isolate 2, rank 2): 32,54 32,55 35,58 43,58 49,64 52,64 53,63 53,61 51,61 47,57 47,48 48,47 54,47 54,45 37,45 32,50
  pour Top (isolate 2, rank 2): 31,85 42,85 48,79 51,77 53,75 53,71 48,71 45,74 45,77 43,79 32,79 30,81
IFB8010
  Top 0.4: R47.1 80.1,59.9 80,57 86.1,57 | 86.55,57 C21.2 | 86.55,57 88,57 88.7,55.9 88.7,53.94 U$1.14 | 86.1,57 86.55,57 | 86.1,57 R46.1
LCDCLK  (via drill 0.6)
  Top 0.4: U$1.24 87,46 v89.1,47.6
  Bottom 0.4: v89.1,47.6 89,49 94,49 94,53 88,59 88,65 89,65 89,70.27 JP2.4
LCDDI  (via drill 0.6)
  Top 0.4: U$1.25 86.25,44.25 v86,44.4 | v91,68.9 89.6,68.9 88,70 88,72.81 JP2.3
  Bottom 0.4: v86,44.4 88.9,44.4 90.5,46.5 90.5,47.5 91,48 95,48 96,49 96,57 97,58 97,62 91,62 v91,68.9
LCDEN  (via drill 0.6)
  Top 0.4: U$1.31 v92.14,46.86 v92.1,46.8 | v93.3,70.8 93,72.73 JP2.5
  Bottom 0.4: v93.3,70.8 93.3,65.9 95,64 99,64 99,57 98,47 94.86,46.86 v92.14,46.86
MASS  (via drill 0.6)  (3 unrouted)
  Top 0.254: 65,110 65,112 RSENS1.2 | 80,82 65,82 U2.4 | C4.- 76,109 | 65,110 65,108 RSENS2.2 | 65,110 RSENS.2
  Top 0.3: 60,84 55,84 55,77
  Top 0.4: 102,46 101,47 JP1.3 100.49,46.95 R43.1 | R44.1 95.15,42.85 95,43 | U$1.32 93.75,44.25 96,42 | U$1.23 86.86,46.86 87,47 | R39.1 79.5,47.5 79.5,51.25 R40.1
  Top 0.406: C7.- 127.55,20.45 124.7,21.4 121.8,21.4 R8.1 120.9,21.1 v119.6,22.3 | C9.2 130.1,34.1 v131.4,32.8 | TRAFO.5 118.5,25.5 119,26 R4.1 | 64.7,28.6 66.7,36.6 | 59.8,83.7 66.4,83.7
  Top 0.5: C4.- 82,109 83,108 83,101 | 66.7,36.6 66.87,36.6 67.27,37 | R23.1 69,49 67,47 77,47
  Top 0.6: 67.27,37 U1.4
  Top 1: v111.7,29.2 111.7,31.35 T3.E
  Bottom 0.254: RSENS2.2 65,108 64.89,107.73
  Bottom 0.406: v111.7,29.2 112,15 MAS1.1 | v131.4,32.8 131.4,31.4 131,31 | 119,22 v119.6,22.3
  Bottom 0.5: 83,102 MINUS.1
  pour Bottom (isolate 2): 132,36 132,12 109,12 109,36
  pour Top (isolate 2, rank 5): 132,36 132,12 109,12 109,36
  pour Bottom (isolate 1, rank 4): 52,100 80,100 80,104 88,104 88,100 134,98 130,2 52,4
  pour Top (isolate 1, rank 4): 52,100 80,100 80,104 86,104 86,100 131,100 132,4 52,4 51,29 65,29 65,40 52,40 52,62 56,71 55,76 55,78 66,83 66,86 52,86
  pour Bottom (isolate 2, rank 2): 65,112 67,112 67,108 68,107 77,107 77,110 85,110 85,107 94,107 94,110 109,110 110,109 110,105 65,105
  pour Top (isolate 2, rank 2): 64,112 67,112 67,108 68,107 77,107 77,110 85,110 85,107 94,107 94,110 109,110 110,109 110,105 64,105
  pour Top (isolate 0.4, rank 4): 83,56 96,56 97,55 97,44 96,43 84,43 83,44
N$1
  Top 0.8: VENT.1 68.73,6.73 68,6 62,6 61,7 61,8 61.1,7 Q5.3
N$2
  Top 0.5: R2.2 62,10.15 Q5.1
N$3
  Top 0.4: U$1.5 96.42,49.42 99,52 100.46,52 JP1.1
N$4  (1 unrouted)
N$5
  Top 0.5: 1LODRV.3 1LODRV.2 | D12.A 69.3,71.7 66,70 61.81,70 R17.2
  Top 0.6: R17.2 60.59,70.64 1LODRV.3
N$6
  Top 0.406: 117.95,33.25 R3.2
  Top 1: TRAFO.1 117.95,33.25
N$7
  Top 0.406: 127.15,33.3 C9.1
  Top 1: TRAFO.2 127.15,33.3
N$8
  Top 0.406: R11.2 130.2,29.15 R6.2
N$9
  Top 0.5: IC1.3 56.08,58.37 R19.1
  Top 0.6: R21.1 61,52.9 61,51 56,51 55.9,51.1 R22.2 55.9,58.35 R19.1
N$10
  Top 0.406: R8.2 120.8,19.1 R13.1 D3.A
N$11  (1 unrouted)
N$12  (1 unrouted)
  Top 0.4: U1.7 59.69,34.23 2HDRV.3
N$13
  Top 0.5: 1HDRV.2 1HDRV.3 | U2.7 62.73,92.27 62.5,92.5
  Top 0.6: 1HDRV.2 62.36,98.36 63,99 68,99 68,95 65,95 62.5,92.5
N$15
  Top 0.5: C17.1 R20.2 58.1,59.9 58.3,59.7 59.33,59.7 IC1.2 59.44,59.6 61.3,59.6 61.9,59 62,59 62,58 62.91,57.09 IC1.5
N$16
  Top 0.6: D11.A 67.95,44 59,44 | 59,44 58.6,44.4 2LODRV.3 | 59,44 59,44.2 58.9,43.97 2LODRV.2
  Top 1: 59,44.2 R18.2
N$17
  Top 0.5: U$2.3 U$2.4 99.4,7 R26.2 98.7,6.9 R25.2
N$18
  Top 0.5: IC1.6 66.64,58.37 67,58 69,58 R24.1 R23.2
N$19
  Top 0.4: U$1.11 91.29,58.3 Q6.1 90.59,61.59 91,62 C19.2
N$20
  Top 0.4: U$1.10 92.14,56.14 93,57 93.41,57 Q6.2 95.41,61.04 C18.2
N$21
  Top 0.4: R36.2 97,36.1 97,37 95.95,38.05 Q8.E 95.85,38 92,38 92,42 91.29,42.71 U$1.30
N$22
  Top 0.4: Q9.E 90.9,36.25 R37.2 91,40.1 91,41 90.42,41.58 U$1.29
N$23
  Top 0.5: R9.2 R27.1
N$24
  Top 0.4: U$1.8 96,52 101,57 LED1.C
N$25
  Top 0.4: Q8.B 93.15,39.95 R37.1
N$26
  Top 0.4: R36.1 94.9,35.1 96,34 96,33.15 Q9.B
N$27  (1 unrouted)
  Top 0.4: U$1.18 81.87,51.18 R40.2
N$28  (1 unrouted)
N$29  (1 unrouted)
  Top 0.5: R10.2 52.1,4.5 50,4.5 49.7,4.8 R12.E 46.79,4.66 R28.1 46,5
N$30
  Top 0.5: 46,9 R28.2 | 46,9 47,10 49.36,10 R12.A | 46,9 45,9 43,7 43,4 -7.55,4 R9.1
N$31
  Top 0.4: 52,9 52,14 52.1,14 R7.2
  Top 0.5: R12.S 50.8,7.8 52,9
N$32
  Top 0.4: U$1.21 83.07,48.58 82.25,47.76 | R39.2 81.89,47.4 82.25,47.76 | R38.2 82.15,48.05 82.25,47.76
N$33
  Top 0.4: Q10.E 87.05,35.05 88,36 88,39 89.58,40.58 U$1.28
  Top 0.5: Q10.E 85.2,33.1 R34.2
N$34
  Top 0.4: R35.1 89.1,33.25 Q10.B
N$35
  Top 0.4: Q11.E 85.95,38.95 R35.2 86.9,39.32 88.71,41.4 U$1.27
N$36
  Top 0.4: R34.1 85,36.15 Q11.B
N$37
  Top 0.4: U$1.4 96.58,48.58 98.1,48.6 99,50 JP1.2
N$38
  Top 0.4: U$1.1 96,45 R44.2 R45.2
N$39
  Top 0.4: U$1.2 96.14,46.86 97.35,45.65 R43.2 R42.2
N$40
  Top 0.4: D13.C C20.1 R46.2
N$42
  Top 0.4: R49.2 96,72.81 JP2.6
O_IFB  (via drill 0.51, 0.51 pad 1.5)  (3 unrouted)
  Top 0.254: JP7.1 105.3,14
  Top 0.406: R24.2 68.1,61.1 67,60 65.8,60 65.5,59.7 64.67,59.7 IC1.7
  Top 1: R24.2 69,62 | 105.3,14 v105.3,16
  Bottom 0.4: v69,63 70,63 74,78 107,78 107,14.68 JP7.1
PUMP+  (1 unrouted)
  Top 0.254: P+2.1 127,12 127.38,12.27
  Top 0.406: P+1.1 130,14 131,15 131,22 130.65,23.35 R11.1 126.4,24.35 TRAFO.3
  pour Top (isolate 2, rank 2): 131,25 131,12 127,12 127,16 130,16 130,23.6 126,23.6 126,25
  pour Bottom (isolate 2, rank 3): 7,24 7,8 30,8 30,14 47,14 50,16 50,103 63,103 63,113 67,113 68,112 68,109 73,109 73,112 87,112 87,108 88,107 93,107 93,112 109,112 112,109 112,107 128,107 128,121 36,121 36,111 29,111 29,118 6,118 6,102 28,102 28,107 37,107 42,112 59,112 59,110 56,107 45,107 43,105 43,21 41,19 29,19 29,24
  pour Top (isolate 2, rank 4): 7,24 7,8 30,8 30,14 47,14 49,16 49,92 50,96 50,103 62,103 63,113 67,113 68,112 68,109 73,109 73,112 87,112 87,108 88,107 93,107 93,112 109,112 112,109 112,107 116,107 116,121 36,121 36,111 29,111 29,118 6,118 6,102 28,102 28,107 37,107 42,112 59,112 59,110 56,107 45,107 43,105 43,21 41,19 29,19 29,24
RED  (2 unrouted)
  Top 0.4: U1.6 59.69,35.5 2HDRV.4 2HDRV.5 51.06,35.41 C12.2
  pour Bottom (isolate 2, rank 3): -11,63 -5,63 -4,62 35,62 36,45 31,45 29,43 29,36 35,30 35,21 34,20 33,20 32,21 32,27 7,27
  pour Top (isolate 2): 33,21 33,35 43,35 44,36 63,36 60,33 45,33 40,24 42,24 40,22 38,22 37,21
  pour Top (isolate 2, rank 3): -11,63 -5,63 -4,62 35,62 36,45 31,45 29,43 29,36 35,30 35,21 34,20 33,20 32,21 32,27 7,27
SCR2
  pour Top (isolate 2): 131,99 131,96 117,96 117,99
  pour Bottom (isolate 2): 136,99 136,96 122,96 122,99
SNUB1
  pour Top (isolate 2, rank 2): 115,99 115,87 108,87 108,99
  pour Bottom (isolate 2, rank 2): 120,99 120,87 113,87 113,99
SNUB2
  pour Top (isolate 2, rank 2): 115,83 115,71 108,71 108,83
  pour Bottom (isolate 2, rank 2): 120,83 120,71 113,71 113,83
SOURCE
  pour Top (isolate 2): 131,83 131,80 117,80 117,83
  pour Bottom (isolate 2): 136,83 136,80 122,80 122,83
TFB  (via drill 0.6, 0.6 pad 1.5)
  Top 0.4: 67.2,16.2 C2.1 | v67,25 v71,25 | U$1.15 87.86,55.86 87,56 v79,56
  Top 0.5: NTC.1 64.73,9.73 67,12 67,12.78 JP7.16 67.22,14.22 v67.2,15.2 67.2,16.2 67.2,16.7 C2.1
  Bottom 0.4: v67.2,15.2 67.2,18.1 v67,25 | v71,25 71,52 76,55 78,55 v79,56
V12  (via drill 0.6, 0.6 pad 1.5)  (3 unrouted)
  Top 0.254: 63,53 R21.2 | V12_2.1 118,11 118,12 118.17,12
  Top 0.4: C8.+ 77.5,15.4 v77.4,15.3
  Top 0.406: C7.+ 124.45,16.45 123,15 120,15 V12_1.1 | V12_1.1 R13.2 | D9.K 116,17 V12_1.1
  Top 0.5: JP7.12 77.38,15.62 v77.4,15.3 77.3,15.4 | 2LODRV.8 53.4,41.6 54,41 | 2LODRV.1 57.5,41 | 1LODRV.8 53.4,67.6 54,67 | 57.5,67 57.75,67.25 1LODRV.1 | 104.85,9.05 U$2.1 | U1.1 68.7,32.96 D8.A
  Top 0.6: 58,82 D10.A | 58,82 59,81 59.46,81.46 U2.1 v60,81 | C14.1 57,81 58,82 | 1LODRV.1 58.69,68 | v67,42 C16.1 | 59.69,42 2LODRV.1 | 64.69,61.7 IC1.8
  Top 1: v67,42 59.69,42 | v65,62.7 64.69,61.7 | v65,53 63,53 | v116,11 V12_2.1 | 57.5,41 54,41 | 57.5,67 54,67 | 57.75,67.25 58,67 v65,67 64,68 C15.1 | v106,9 104.85,9.05
  Bottom 0.4: 67,29 69,29 69,18 76.5,18 C8.+ 77.5,16.2 77.3,16
  Bottom 0.5: 77.3,16.8 77.3,16 77.3,15.4 v77.4,15.3 | v106,9 105,9 106,8
  Bottom 1: 67,29 v67,42 v65,53 v65,62.7 v65,67 65,74 v60,81 | v77.4,15.3 77.3,11 80,8 106,8 116,8 v116,11
  other vias: 68.6,29.6
  pour Top (isolate 2): 125,18 125,12 116,12 116,17 123,17
  pour Top (isolate 1.5, rank 2): 55,82 61,82 61,80 55,80
VB1
  Top 0.5: 55.4,96.6 1HDRV.8 | 60,96.5 1HDRV.1 | 61,88.27 U2.8 | C11.1 64.35,97.45 63.4,96.5
  Top 1: 55.4,96.6 56,96 58,96 | 58,96 60,96 60,96.5 | 58,96 D10.K 58.6,91.4 61,89 61,88.27
  pour Top (isolate 1.5, rank 2): 55,97 65,97 65,95 62,92 62,88 61,89 59,90 54,90 54,96
VB2
  Top 0.4: C12.1 54.25,31.45 2HDRV.8 2HDRV.1 62.5,31.59 D8.K
  Top 0.5: D8.K 61.9,32.1 63,33 62.23,33 U1.8
VDD  (via drill 0.6, 0.6 pad 1.5)  (1 unrouted)
  Top 0.4: U$1.26 87.86,42.86 87,42 83.1,42 v82.7,43 | U$1.17 84.25,52.75 v84,53 | R45.1 99.65,42.65 v100,43 R42.1 | JP2.1 83.11,71.11 v83,70 | v78,48.3 v78,58 | v87,67 v96,67 R49.1 | v102,68 R48.1 | R38.1 80.45,49.65 v80.5,49.7 | JP7.14 72,13.3 v72.3,15.2 72.3,19.6 72.6,19.9 74.9,19.9 v77,21
  Top 0.5: NTC.2 71.73,9 VENT.2 | VENT.2 73.73,9.27 75,8 76.3,8 C6.+ | JP7.14 72.3,9.57 VENT.2 | v94,4.5 94.1,4.4 R26.1 104.4,4.4 105,5 105,5.25 U$2.2
  Bottom 0.4: v77,21 77,42.2 77.24,42.26 | 77.24,42.26 79,43 v82.7,43 v100,43 | v84,53 84,52 81,50.2 v80.5,49.7 v78,48.3 78,43.32 77.24,42.26 | 83,67 83,66 79,66 78,63 v78,58 | 83,67 v83,70 | 83.11,70.11 83.11,68.89 83,67 | 83,67 v87,67 | v96,67 v102,68
  Bottom 0.5: v94,4.5 78,4.5 74.5,9 72.27,9 VENT.2
VFB  (via drill 0.6)
  Top 0.4: C10.1 70.9,19.9 v71,21 | v89.2,51 89.6,52 89.6,53.33 U$1.13
  Top 0.5: 54.1,17.1 60,20 68,20 69.7,17.2 | 69.7,17.2 69.7,13.94 | 69.7,17.2 C10.1
  Top 0.8: R7.1 54.1,17.1 | 69.7,13.94 JP7.15
  Bottom 0.4: v71,21 74,21 75,23 75,49 81,52 82,53 82,55 86,55 v89.2,51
